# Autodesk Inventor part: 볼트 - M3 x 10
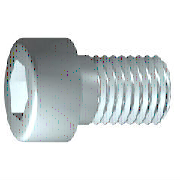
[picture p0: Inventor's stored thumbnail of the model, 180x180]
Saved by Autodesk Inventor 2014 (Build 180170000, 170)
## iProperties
Created: 2012-02
Part Number: 볼트 - M3 x 10
Material: 스테인리스강
Description: 6각 소켓 머리 캡 나사
Document SubType Name: Modeling
Standard: ISO 4762
Designer: mduedu
Standard Revision: Fourth edition 2004-03-01
Standards Organization: ISO
Language: ko-KR
Size Designation: M3 x 10
Categories: <MemberInstance><Categories><Category DisplayName="조임쇠" InternalName="e4da775c-781d-43d5-af7c-5136215cf5a6" Mnemonic="FSTN"><Category DisplayName="볼트" InternalN
Density: 7.75 g/cm^3
Appearance: 반광택
IsCustomPart: 0
Author: mduedu
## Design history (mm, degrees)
sketch "스케치1"
  geometry: L1 (-0.867, 0)-(10, 0); L2 (10, 0)-(10, 1.5); L3 (10, 1.5)-(1.25, 1.5); L4 (1.25, 1.5)-(0.943, 1.5); L5 (0.943, 1.5)-(0, 1.5); L6 (0, 1.5)-(0, 2.75); L7 (0, 2.75)-(-3, 2.75); L8 (-3, 2.75)-(-3, 1.443); L9 (-3, 1.443)-(-1.7, 1.443); L10 (-1.7, 1.443)-(-0.867, 0); L11 (-5.6, 0)-(12.6, 0) reference; L12 (0, -0.55)-(0, 3.3) reference; L13 (1.25, 1.5)-(0, 1.5)
  constraints: 22 end point, 6 parallel, 2 collinear, 2 perpendicular, 1 horizontal, 1 point on line
  dimensions: "d1" = 8.75 distance from line of L3.end L2 (= GEL); "d2" = 0.30683 distance of L4.end L3.end (computed from GAL); "d3" = 3 distance between parallel lines of L8 L6 (= KOH); "d4" = 1.3 distance of L8.end L9.end (= INTI); "d5" = 60 deg angle of L10 L1; "d6" = 3 diameter of L3 L1 (= GD); "d7" = 3 diameter of L5 L1 (= BDM); "d8" = 2.88675 diameter of L9 L1 (= 1.1547 x SW); "d9" = 5.5 diameter of L7 L1 (= KOD); "d26" = 10 distance between parallel lines of L12 L2 (= NLG)
revolve "본체" sketch "스케치1" stored, may be unused: angle "d10" = 90 deg
sketch "스케치2"
  geometry: L1 (0, -3.85)-(0, 3.85) reference; L2 (-3.85, 0)-(3.85, 0) reference; L3 (1.443, 0)-(0.722, -1.25); L4 (0.722, -1.25)-(-0.722, -1.25); L5 (-0.722, -1.25)-(-1.443, 0); L6 (-1.443, 0)-(-0.722, 1.25); L7 (-0.722, 1.25)-(0.722, 1.25); L8 (0.722, 1.25)-(1.443, 0); 2 further points
  constraints: 12 end point, 1 coincident, 1 horizontal alignment, 1 point on line, 12 other
extrude "슬롯" join sketch "스케치2" stored distance "d11" = 10; taper "d12" = 0 deg
workplane "Work Plane1"
fillet "Fillet2" dims "d30" = 0.1 (= R)
body "Solid1"
fillet "모깎기1" dims "d17" = 0.3 (= RR)
feature "스레드" dims "d13" = 8.75 (= GEL), "d14" = 0
chamfer "모따기1" distance "d15" = 0.30673 (= -0.5 x SPD + 0.5 x GD); stored, may be unused: second distance "d16" = 0.30673 (= GUL), angle "d27" = 45 deg
other parameters: "GD" = 3 [user parameter; used in 2 equation terms], "NLG" = 10 [user parameter; used in 1 equation term], "GEL" = 8.75 [user parameter; used in 2 equation terms], "KOD" = 5.5 [user parameter; used in 1 equation term], "KOH" = 3 [user parameter; used in 1 equation term], "INTI" = 1.3 [user parameter; used in 1 equation term], "GAL" = 0.30673 (= 0.61345 x PTC) [user parameter; used in 1 equation term], "GUL" = 0.30673 (= 0.61345 x PTC) [user parameter; used in 1 equation term], "BDM" = 3 (= NND) [user parameter; used in 1 equation term], "SW" = 2.5 [user parameter; used in 2 equation terms], "RR" = 0.3 [user parameter; used in 1 equation term], "SPD" = 2.38655 (= NND - 1.2269 x PTC) [user parameter; used in 1 equation term], "d19" = 0, "d28" = 0, "d29" = 0, "R" = 0.1 [user parameter; used in 1 equation term], "TOA" = 30 deg [user parameter], "GD1" = 2.38655 (= THREADDIA - 1.2269 x PTC) [user parameter], "THREADDIA" = 3 [user parameter; used in 1 equation term], "FAWI" = 45 deg [user parameter], "PTC" = 0.5 [user parameter; used in 5 equation terms], "NND" = 3 [user parameter; used in 2 equation terms], "E0" = 2.8875 (= 1.155 x SW) [user parameter]
